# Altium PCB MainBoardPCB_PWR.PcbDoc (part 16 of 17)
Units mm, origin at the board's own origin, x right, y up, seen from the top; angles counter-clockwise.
Board outline 333.63 x 349.38 mm, 16 copper layers (L1, L2 (GND), L3 (Sign), L4 (GND), L5 (Sign), L6 (PWR/GND), L7(PWR/GND), L8 (PWR/GND), L9 (PWR/GND), L10 (PWR/GND), L11 (PWR/GND), L12 (Sign), L13 (GND), L14 (Sign), L15 (GND), L16), stack 2.503 mm thick; 2187 components, 1615 nets, 7987 pads, 1695 vias.
Unrouted connection lines stored in the file: 4757.
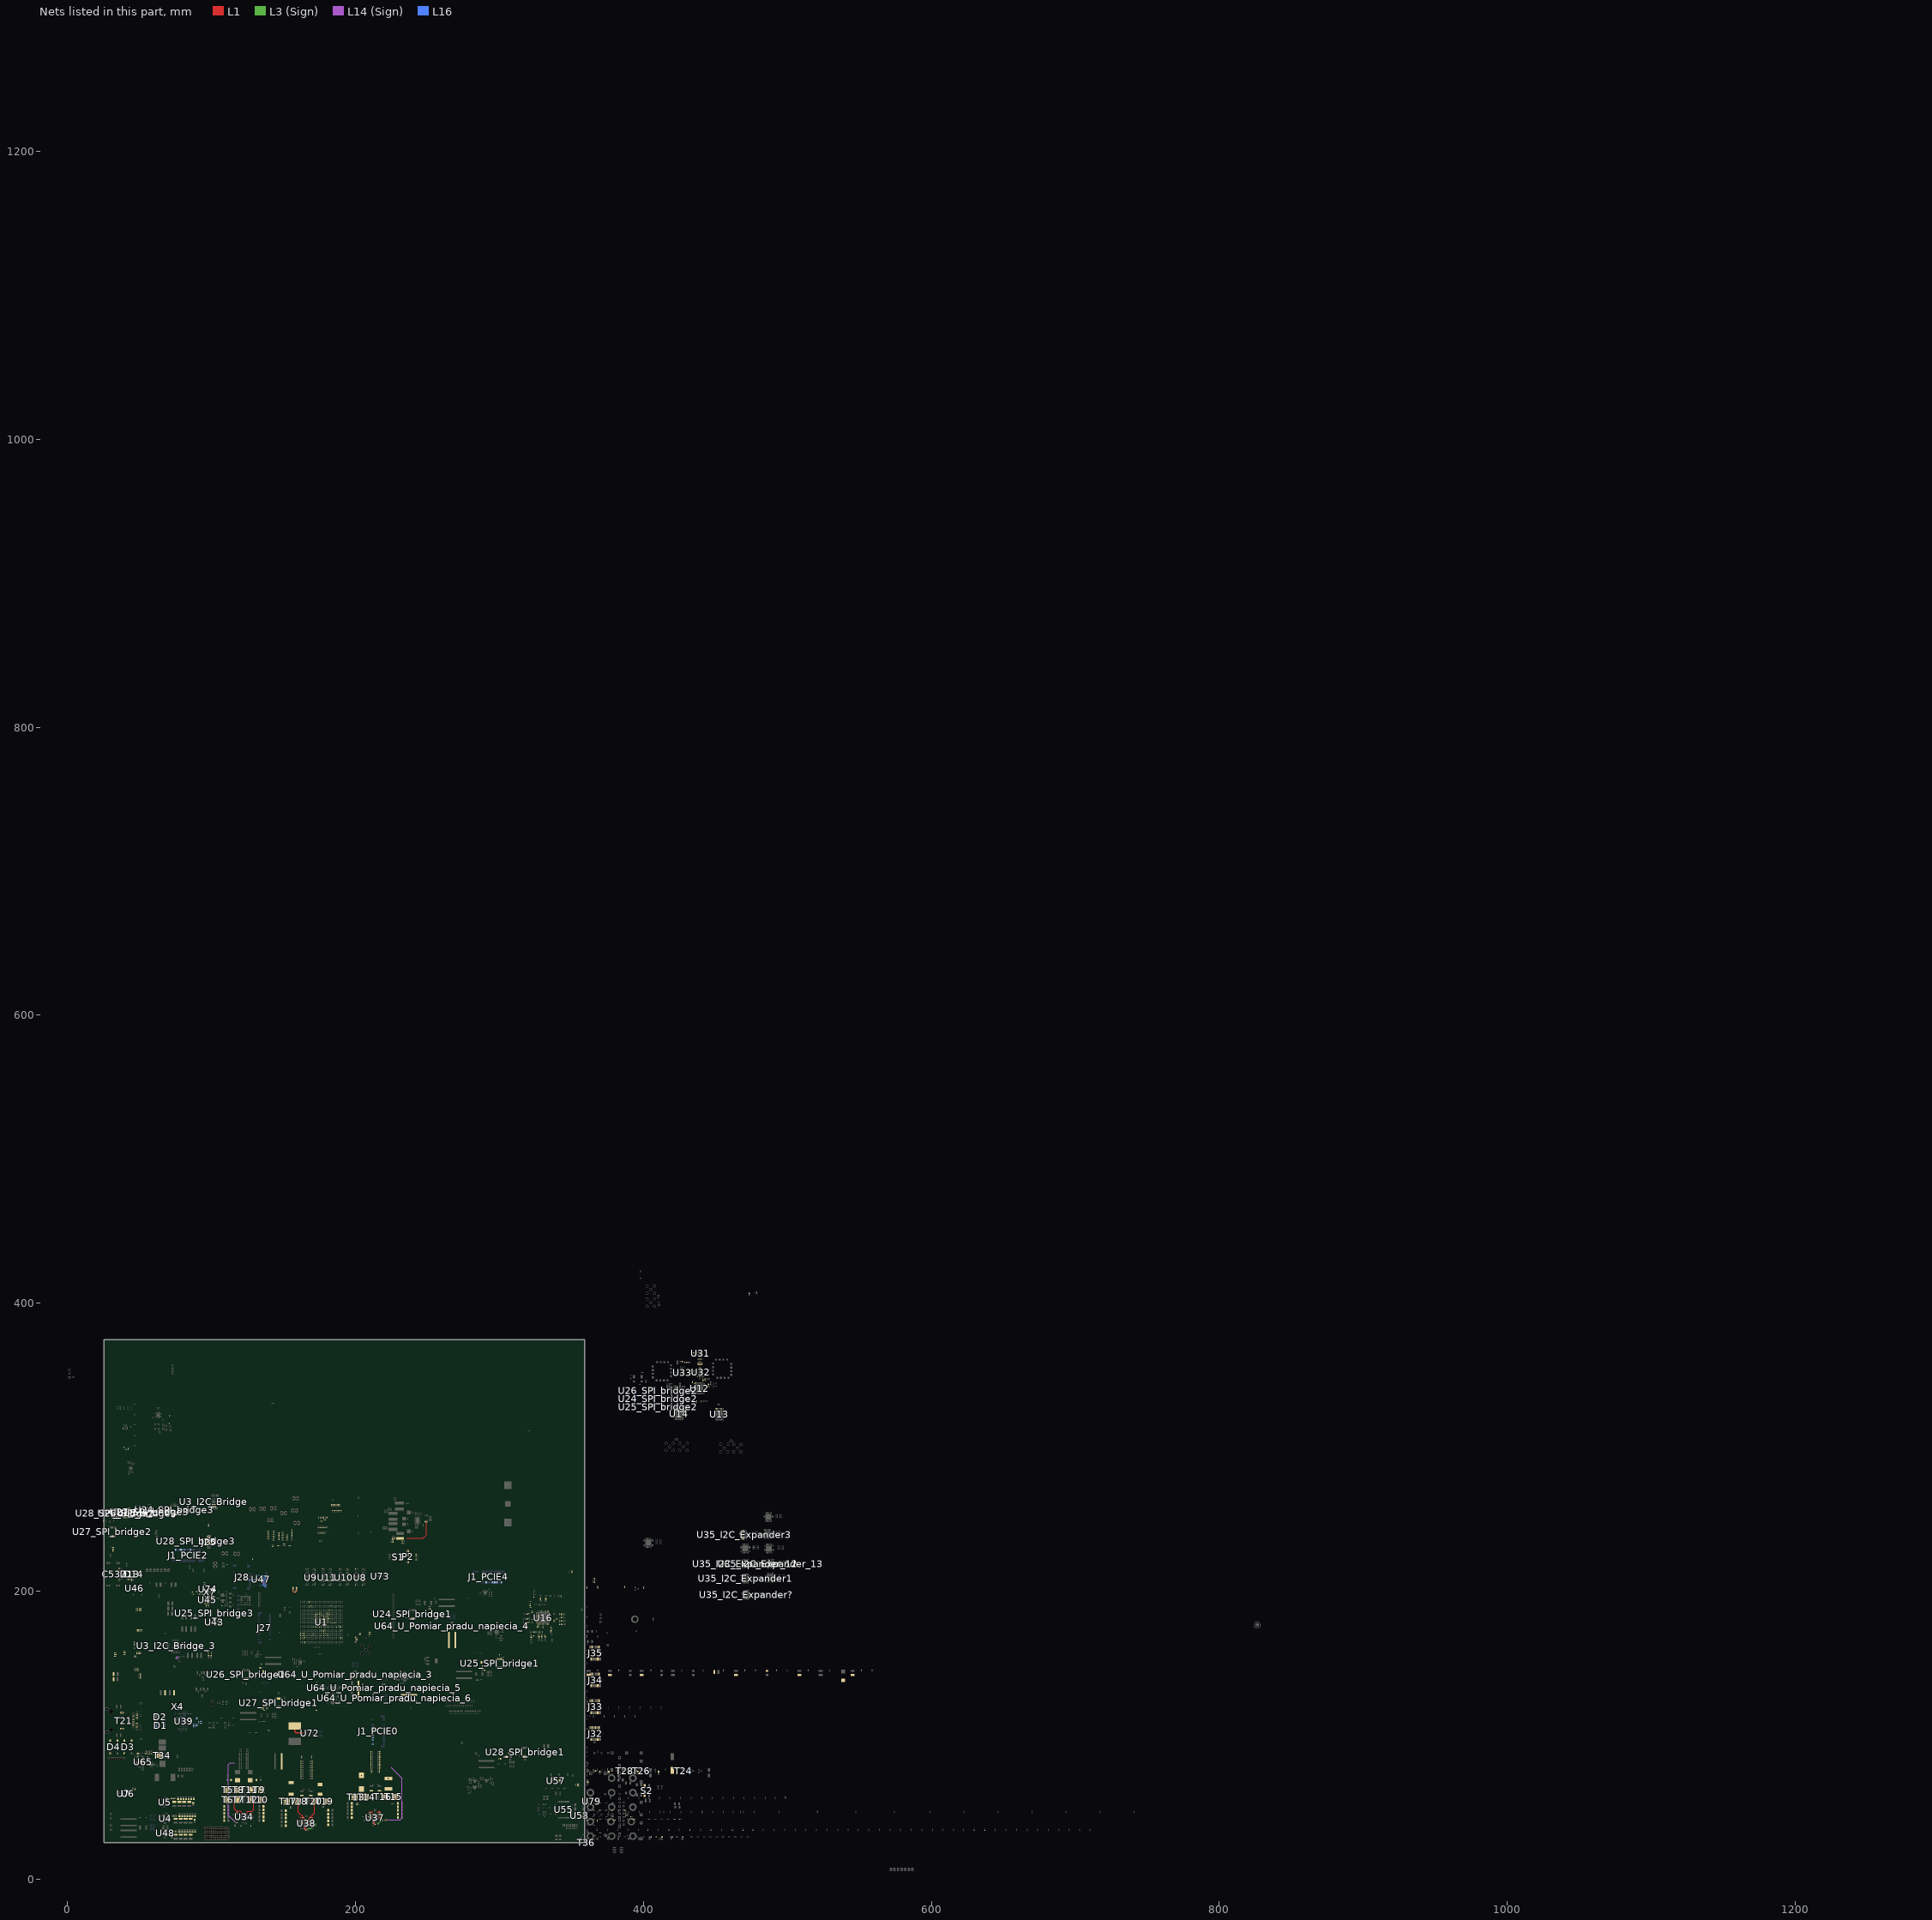
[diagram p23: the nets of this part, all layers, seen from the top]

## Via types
v1: diameter 0.5, hole 0.2, L1 to L16, 786 vias
v2: diameter 0.5/0.35/0.35/0.35/0.35/0.35/0.35/0.35/0.35/0.35/0.35/0.35/0.35/0.35/0.35/0.5 (per signal layer), hole 0.15, L1 to L16, tented both sides, 164 vias
v3: diameter 2.54, hole 1.02, L1 to L16, 152 vias
v4: diameter 0.5/0.35/0.35/0.35/0.35/0.35/0.35/0.35/0.35/0.35/0.35/0.35/0.35/0.35/0.35/0.5 (per signal layer), hole 0.2, L1 to L16, tented both sides, 100 vias
v5: diameter 0.45, hole 0.15, L1 to L16, 79 vias
v6: diameter 0.35/0/0.35 (per signal layer), hole 0.127, L1 to L3 (Sign), tented both sides, 78 vias
v7: diameter 0.45/0.45/0.45/0.45/0.45/0.45/0.45/0.45/0.45/0.45/0.45/0.45/0.45/0.45/0.45/0.45 (per signal layer), hole 0.15, L1 to L16, 65 vias
v8: diameter 0.4, hole 0.15, L1 to L16, 61 vias
v9: diameter 0.2, hole 0.1, L1 to L16, 35 vias
v10: diameter 0.5, hole 0.2, L1 to L16, tented both sides, 32 vias
v11: diameter 0.2/0/0.2 (per signal layer), hole 0.1, L1 to L3 (Sign), 28 vias
v12: diameter 0.4, hole 0.2, L1 to L16, 16 vias
v13: diameter 0.25, hole 0.2, L1 to L16, 16 vias
v14: diameter 0.3, hole 0.2, L1 to L16, 15 vias
v15: diameter 0.5/0.35/0.35/0.35/0.35/0.35/0.35/0.35/0.35/0.35/0.35/0.35/0.35/0.35/0.35/0.45 (per signal layer), hole 0.15, L1 to L16, tented both sides, 10 vias
v16: diameter 5, hole 3, L1 to L16, 9 vias
v17: diameter 0.2/0/0.2 (per signal layer), hole 0.1, L1 to L3 (Sign), tented both sides, 9 vias
v18: diameter 0.35/0/0.35 (per signal layer), hole 0.127, L1 to L3 (Sign), 7 vias
v19: diameter 0.35/0/0.35 (per signal layer), hole 0.127, L14 (Sign) to L16, tented both sides, 5 vias
v20: diameter 1.65, hole 1.65, L1 to L16, 4 vias
v21: diameter 1.15, hole 1.15, L1 to L16, 4 vias
v22: diameter 0.35, hole 0.127, L1 to L2 (GND), 2 vias
v23: diameter 0.4, hole 0.2, L1 to L16, tented both sides, 2 vias
v24: diameter 0.35, hole 0.127, L1 to L2 (GND), tented both sides, 2 vias
v25: diameter 0.508, hole 0.127, L1 to L2 (GND), 2 vias
v26: diameter 0.508, hole 0.127, L2 (GND) to L3 (Sign), 2 vias
v27: diameter 0.35, hole 0.127, L3 (Sign) to L6 (PWR/GND), tented both sides, 2 vias
v28: diameter 0.5, hole 0.2, L3 (Sign) to L6 (PWR/GND), tented both sides, 2 vias
v29: diameter 5.5, hole 3.5, L1 to L16, 1 vias
v30: diameter 0.45/0.45/0.45 (per signal layer), hole 0.15, L1 to L3 (Sign), 1 vias
v31: diameter 0.35/0.35/0.35 (per signal layer), hole 0.127, L1 to L3 (Sign), tented both sides, 1 vias
v32: diameter 0.45/0/0.45 (per signal layer), hole 0.15, L1 to L3 (Sign), tented both sides, 1 vias
v33: diameter 0.45/0/0.45 (per signal layer), hole 0.2, L14 (Sign) to L16, tented both sides, 1 vias
v34: diameter 0.35, hole 0.127, L2 (GND) to L3 (Sign), 1 vias

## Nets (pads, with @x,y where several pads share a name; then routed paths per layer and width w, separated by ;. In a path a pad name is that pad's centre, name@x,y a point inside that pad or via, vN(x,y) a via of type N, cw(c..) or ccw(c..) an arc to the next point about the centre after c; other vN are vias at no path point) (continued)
PWR_OUT_20V: C347.2 C348.2 C352.2 C353.2 C371.2 C372.2 C373.2 C374.2 C375.2 C376.2 C391.1 C392.2 C396.2 C397.1 C400.2 C401.2 C402.2 C403.2 C404.2 C405.2 C432.1 C433.2 C437.2 C438.1 C441.2 C442.2 C443.2 C444.2 C445.2 C446.2 C766.1 C767.1 C768.1 C769.1 C770.2 C771.2 C772.2 C773.2 C774.2 C775.2 C776.2 C777.2 C778.2 C779.2 C780.2 C781.2 R266.2 R268.1 R285.1 R303.1 R612.2 R614.2 R621.2 R622.2 R628.2 R686.2 T5.5 T5.6 T5.7 T5.8 T6.5 T6.6 T6.7 T6.8 T9.5 T9.6 T9.7 T9.8 T10.5 T10.6 T10.7 T10.8 T13.5 T13.6 T13.7 T13.8 T15.5 T15.6 T15.7 T15.8 T17.5 T17.6 T17.7 T17.8 T19.5 T19.6 T19.7 T19.8 U48.1 U48.8
  other v1: 95.25,27.75 96,27.75 96.75,27.75 97.5,27.75 98.25,27.75 99,27.75 99.75,27.75 100.5,27.75 101.25,27.75 102,27.75 102.75,27.75 103.5,27.75 104.25,27.75 105,27.75 105.75,27.75 106.5,27.75 107.25,27.75 108,27.75 108.75,27.75 109.5,27.75 110.25,27.75 111,27.75 95.625,28.5 96.375,28.5 97.125,28.5 97.875,28.5 98.625,28.5 99.375,28.5 100.125,28.5 100.875,28.5 101.625,28.5 102.375,28.5 103.125,28.5 103.875,28.5 104.625,28.5 105.375,28.5 106.125,28.5 106.875,28.5 107.625,28.5 108.375,28.5 109.125,28.5 109.875,28.5 110.625,28.5 111.375,28.5 112.125,28.5 95.25,29.25 96,29.25 96.75,29.25 97.5,29.25 98.25,29.25 99,29.25 99.75,29.25 100.5,29.25 101.25,29.25 102,29.25 102.75,29.25 103.5,29.25 104.25,29.25 105,29.25 105.75,29.25 106.5,29.25 107.25,29.25 108,29.25 108.75,29.25 109.5,29.25 110.25,29.25 111,29.25 111.75,29.25 95.625,30 96.375,30 97.125,30 97.875,30 98.625,30 99.375,30 100.125,30 100.875,30 101.625,30 102.375,30 103.125,30 103.875,30 104.625,30 105.375,30 106.125,30 106.875,30 107.625,30 108.375,30 109.125,30 109.875,30 110.625,30 111.375,30 112.125,30 95.25,30.75 96,30.75 96.75,30.75 97.5,30.75 98.25,30.75 99,30.75 99.75,30.75 100.5,30.75 101.25,30.75 102,30.75 102.75,30.75 103.5,30.75 104.25,30.75 105,30.75 105.75,30.75 106.5,30.75 107.25,30.75 108,30.75 108.75,30.75 109.5,30.75 110.25,30.75 111,30.75 111.75,30.75 95.625,31.5 96.375,31.5 97.125,31.5 97.875,31.5 98.625,31.5 99.375,31.5 100.125,31.5 100.875,31.5 101.625,31.5 102.375,31.5 103.125,31.5 103.875,31.5 104.625,31.5 105.375,31.5 106.125,31.5 106.875,31.5 107.625,31.5 108.375,31.5 109.125,31.5 109.875,31.5 110.625,31.5 111.375,31.5 112.125,31.5 95.25,32.25 96,32.25 96.75,32.25 97.5,32.25 98.25,32.25 99,32.25 99.75,32.25 100.5,32.25 101.25,32.25 102,32.25 102.75,32.25 103.5,32.25 104.25,32.25 105,32.25 105.75,32.25 106.5,32.25 107.25,32.25 108,32.25 108.75,32.25 109.5,32.25 110.25,32.25 111,32.25 111.75,32.25 95.625,33 96.375,33 97.125,33 97.875,33 98.625,33 99.375,33 100.125,33 100.875,33 101.625,33 102.375,33 103.125,33 103.875,33 104.625,33 105.375,33 106.125,33 106.875,33 107.625,33 108.375,33 109.125,33 109.875,33 110.625,33 111.375,33 112.125,33 95.25,33.75 96,33.75 96.75,33.75 97.5,33.75 98.25,33.75 99,33.75 99.75,33.75 100.5,33.75 101.25,33.75 102,33.75 102.75,33.75 103.5,33.75 104.25,33.75 105,33.75 105.75,33.75 106.5,33.75 107.25,33.75 108,33.75 108.75,33.75 109.5,33.75 110.25,33.75 111,33.75 111.75,33.75 95.625,34.5 96.375,34.5 97.125,34.5 97.875,34.5 98.625,34.5 99.375,34.5 100.125,34.5 100.875,34.5 101.625,34.5 102.375,34.5 103.125,34.5 103.875,34.5 104.625,34.5 105.375,34.5 106.125,34.5 106.875,34.5 107.625,34.5 108.375,34.5 109.125,34.5 109.875,34.5 110.625,34.5 111.375,34.5 112.125,34.5 95.25,35.25 96,35.25 96.75,35.25 97.5,35.25 98.25,35.25 99,35.25 99.75,35.25 100.5,35.25 101.25,35.25 102,35.25 102.75,35.25 103.5,35.25 104.25,35.25 105,35.25 105.75,35.25 106.5,35.25 107.25,35.25 108,35.25 108.75,35.25 109.5,35.25 110.25,35.25 111,35.25 111.75,35.25 95.625,36 96.375,36 97.125,36 97.875,36 98.625,36 99.375,36 100.125,36 100.875,36 101.625,36 102.375,36 103.125,36 103.875,36 104.625,36 105.375,36 106.125,36 106.875,36 107.625,36 108.375,36 109.125,36 109.875,36 110.625,36 111.375,36
  other v12: 67.617,31.412 68.417,31.412
PWR_Switch1_En: U6.A2 U35_I2C_Expander1.3
PWR_Switch1_Flag: U35_I2C_Expander1.2
PWR_Switch2_En: U7.A2 U35_I2C_Expander1.22
PWR_Switch2_Flag: U35_I2C_Expander1.18
PWR_SwitchR1_Flag: R29.1 U6.A3
PWR_SwitchR2_Flag: R30.1 U7.A3
RAM_DDR4_VTT: C722.2 C723.2 R31.2 R32.2 R33.2 R34.2 R35.2 R36.2 R37.2 R38.2 R39.2 R40.2 R41.2 R42.2 R43.2 R44.2 R45.2 R46.2 R47.2 R48.2 R49.2 R50.2 R51.2 R53.2 R55.2 R57.2 R59.2 R689.1 U73.8
RAM_Vcc1V2: C36.2 C220.1 C222.1 C223.2 C224.2 C225.2 C226.2 C227.2 C228.2 C229.2 C230.2 C231.2 C232.2 C233.2 C234.2 C235.2 C236.2 C237.2 C238.2 C239.2 C240.2 C241.2 C242.2 C244.1 C246.1 C247.2 C248.2 C249.2 C250.2 C251.2 C252.2 C253.2 C254.2 C255.2 C256.2 C257.2 C258.2 C259.2 C260.2 C261.2 C262.2 C263.2 C264.2 C265.2 C266.2 C741.2 C760.1 C761.2 R58.2 R165.2 R166.2 R169.2 R171.2 R297.2 R448_U_Pomiar_pradu_napiecia_4.2 R695.1 U1.A6 U1.B8 U1.C6 U1.D8 U1.E6 U1.G6 U1.J6 U1.L6 U1.M25 U1.N6 U1.R6 U1.T18 U1.T20 U1.T21 U1.U6 U8.A1 U8.A6 U8.B3 U8.B6 U8.C1 U8.D1 U8.D6 U8.F2 U8.F5 U8.G1 U8.G4 U8.G6 U8.J1 U8.J2 U8.J5 U8.J6 U8.L1 U8.L6 U8.R1 U8.T6 U9.A1 U9.A6 U9.B3 U9.B6 U9.C1 U9.D1 U9.D6 U9.F2 U9.F5 U9.G1 U9.G4 U9.G6 U9.J1 U9.J2 U9.J5 U9.J6 U9.L1 U9.L6 U9.R1 U9.T6 U10.A1 U10.A6 U10.B3 U10.B6 U10.C1 U10.D1 U10.D6 U10.F2 U10.F5 U10.G1 U10.G4 U10.G6 U10.J1 U10.J2 U10.J5 U10.J6 U10.L1 U10.L6 U10.R1 U10.T6 U11.A1 U11.A6 U11.B3 U11.B6 U11.C1 U11.D1 U11.D6 U11.F2 U11.F5 U11.G1 U11.G4 U11.G6 U11.J1 U11.J2 U11.J5 U11.J6 U11.L1 U11.L6 U11.R1 U11.T6 U64_U_Pomiar_pradu_napiecia_4.8 U64_U_Pomiar_pradu_napiecia_4.9 | length 50.7
  L1 w0.254: R297.2@221.201,41.215 222.24,41.215 v9(222.26,41.234)
  L14 (Sign) w0.254: v9(222.26,41.234) 231.218,41.234 232.456,42.473 232.456,69.878 v9@224.342,77.993
  L16 w0.254: v9@224.342,77.993 v9(224.342,77.996)
RAM_VrefA: C221.1 R166.1 R168.1 U8.M1
RAM_VrefB: C243.1 R169.1 R170.1 U10.M1
RAM_VrefC: C219.1 R165.1 R167.1 U9.M1
RAM_VrefD: C245.1 R171.1 R172.1 U11.M1
RefClk_Si53323_N: R253.1 R255.2 U31.7
RefClk_Si53323_P: C341.2 R252.1 R254.2 U31.6
RESET_N: R712.1 R713.2 U39.43
RESETB: U45.27 U74.4
RST_brigde: R757.1 U3_I2C_Bridge_3.24 U35_I2C_Expander?.28
SD_Card_CLK: J28.5 U47.C5 | length 6.8
  L16 w0.098: J28.5@126.749,207.781 129.739,207.781 130.112,208.153 U47.C5@133.439,208.153
SD_Card_en: R382.1 U47.C2
SetClk_Si53323_2: T36.1 U1.K12
SFP0_ABS: J32.6 R65.1
SFP0_LOS: J32.8 R66.1 U35_I2C_Expander3.28
SFP0_RS0: J32.7 R72.1 R74.2
SFP0_RS1: J32.9 R71.1 R73.2
SFP0_Rx_N: J32.19 U1.D5
SFP0_Rx_P: J32.18 U1.D6
SFP0_Tx_N: J32.12 U1.D1
SFP0_Tx_P: J32.13 U1.D2
SFP0_TxDis: J32.3 R68.1 U35_I2C_Expander3.27
SFP0_TxF: J32.2 R67.1 U35_I2C_Expander3.26
SFP0_VccR: C37.2 C38.1 J32.15 L1.2
SFP0_VccT: C39.2 C40.1 J32.16 L2.2
SFP1_ABS: J33.6 R135.1
SFP1_GND: R143.1 R144.1
SFP1_LOS: J33.8 R136.1 U35_I2C_Expander3.4
SFP1_RS0: J33.7 R142.1 R144.2
SFP1_RS1: J33.9 R141.1 R143.2
SFP1_Rx_N: J33.19 U1.C7 | length 2.1
  L14 (Sign) w0.072: 75.168,153.381 ccw(c75.168,156.118) 77.104,154.183
SFP1_Rx_P: J33.18 U1.C8 | length 2
  L14 (Sign) w0.072: 75.167,153.581 ccw(c75.167,156.121) 76.963,154.325
SFP1_Tx_N: J33.12 U1.C3
SFP1_Tx_P: J33.13 U1.C4
SFP1_TxDis: J33.3 R138.1 U35_I2C_Expander3.1
SFP1_TxF: J33.2 R137.1 U35_I2C_Expander3.24
SFP2_ABS: J34.6 R145.1
SFP2_GND: R153.1 R154.1
SFP2_LOS: J34.8 R146.1 U35_I2C_Expander3.3
SFP2_RS0: J34.7 R152.1 R154.2
SFP2_RS1: J34.9 R151.1 R153.2
SFP2_Rx_N: J34.19 U1.B5
SFP2_Rx_P: J34.18 U1.B6
SFP2_Tx_N: J34.12 U1.B1
SFP2_Tx_P: J34.13 U1.B2
SFP2_TxDis: J34.3 R148.1 U35_I2C_Expander3.17
SFP2_TxF: J34.2 R147.1 U35_I2C_Expander3.19
SFP3_ABS: J35.6 R155.1
SFP3_GND: R163.1 R164.1
SFP3_LOS: J35.8 R156.1 U35_I2C_Expander3.21
SFP3_RS0: J35.7 R162.1 R164.2
SFP3_RS1: J35.9 R161.1 R163.2
SFP3_Rx_N: J35.19 U1.A7
SFP3_Rx_P: J35.18 U1.A8
SFP3_Tx_N: J35.12 U1.A3
SFP3_Tx_P: J35.13 U1.A4
SFP3_TxDis: J35.3 R158.1 U35_I2C_Expander3.18
SFP3_TxF: J35.2 R157.1 U35_I2C_Expander3.2
SFP_IO_nReset: R756.1 U35_I2C_Expander3.14 U35_I2C_Expander?.1
SGMI_C_Rx_N: C484.1 U1.G26
SGMI_C_Rx_P: C483.1 U1.G25
SGMI_C_Tx_N: C482.1 U1.G30
SGMI_C_Tx_P: C479.1 U1.G29
SGMI_CLK_Out_N: R320.1 R321.1 R326.2 U39.34
SGMI_CLK_Out_P: R319.1 R321.2 R325.2 U39.33
SGMI_Rx_N: C484.2 U39.28
SGMI_Rx_P: C483.2 U39.27
SGMI_Tx_N: C482.2 R323.1 R328.2 U39.36
SGMI_Tx_P: C479.2 R322.1 R327.2 U39.35
Si53323_1_Q1_N: C330.1 R249.1 U31.9
Si53323_1_Q1_P: C325.1 R246.2 U31.10
Si53323_1_Q2_LVDS_N: C725.2 R386.2 R387.2 U1.AK4
Si53323_1_Q2_LVDS_P: C724.2 U1.AJ4
Si53323_1_Q2_N: R301.1 R385.2 U31.12
Si53323_1_Q2_P: R291.1 R384.2 U31.11
Si53323_2_CLK1_N: C330.2 R245.2 R248.2 R251.2 U32.4
Si53323_2_CLK1_P: C325.2 R245.1 R247.2 R250.2 U32.3
Si53323_2_Q1_N: C54.2 R537.2 U32.10
Si53323_2_Q1_P: C53.2 R536.1 U32.9
Si53323_2_Q2_LVDS_N: C727.2 R486.2 R487.2
Si53323_2_Q2_LVDS_P: C726.2
Si53323_2_Q2_N: R483.1 R485.2 U32.12
Si53323_2_Q2_P: R482.1 R484.2 U32.11
SMCLK_PCIE0: J1_PCIE0.26 R559_I2C_Bridge.1 U3_I2C_Bridge.2
SMCLK_PCIE1: R227_I2C_Bridge.1 U3_I2C_Bridge.4
SMCLK_PCIE2: J1_PCIE2.26 R225_I2C_Bridge.1 U3_I2C_Bridge.6
SMCLK_PCIE3: R223_I2C_Bridge.1 U3_I2C_Bridge.8
SMCLK_PCIE4: J1_PCIE4.26 R9_I2C_Bridge.1 U3_I2C_Bridge.11
SMDAT_PCIE0: J1_PCIE0.28 R560_I2C_Bridge.1 U3_I2C_Bridge.1
SMDAT_PCIE1: R558_I2C_Bridge.1 U3_I2C_Bridge.3
SMDAT_PCIE2: J1_PCIE2.28 R226_I2C_Bridge.1 U3_I2C_Bridge.5
SMDAT_PCIE3: R224_I2C_Bridge.1 U3_I2C_Bridge.7
SMDAT_PCIE4: J1_PCIE4.28 R10_I2C_Bridge.1 U3_I2C_Bridge.10
SPI1_CLK: J25.1 R132.2 R803.1 U15.14 U24_SPI_bridge2.3 U24_SPI_bridge3.3 U25_SPI_bridge2.3 U25_SPI_bridge3.3 U26_SPI_bridge2.3 U26_SPI_bridge3.3 U27_SPI_bridge2.3 U27_SPI_bridge3.3 U28_SPI_bridge2.3 U28_SPI_bridge2.14 U28_SPI_bridge3.3
SPI1_CLK: 
SPI1_CS: J25.4 R123.1 R124.1 R806.1 U15.11 U24_SPI_bridge2.6 U24_SPI_bridge3.6 U25_SPI_bridge2.6 U25_SPI_bridge3.6 U26_SPI_bridge2.6 U26_SPI_bridge3.6 U27_SPI_bridge2.6 U27_SPI_bridge3.6 U28_SPI_bridge2.6 U28_SPI_bridge3.6
SPI1_MISO: J25.3 R807.1 U15.13 U24_SPI_bridge2.4 U24_SPI_bridge3.4 U25_SPI_bridge2.4 U25_SPI_bridge3.4 U26_SPI_bridge2.4 U26_SPI_bridge3.4 U27_SPI_bridge2.4 U27_SPI_bridge3.4 U28_SPI_bridge2.4 U28_SPI_bridge3.4
SPI1_MISO: U12.51 U26_SPI_bridge2.13
SPI1_MOSI: U35_I2C_Expander_13.19
SPI1_MOSI: J25.2 R808.1 U12.52 U15.12 U24_SPI_bridge2.5 U24_SPI_bridge3.5 U25_SPI_bridge2.5 U25_SPI_bridge3.5 U26_SPI_bridge2.5 U26_SPI_bridge2.12 U26_SPI_bridge3.5 U27_SPI_bridge2.5 U27_SPI_bridge3.5 U28_SPI_bridge2.5 U28_SPI_bridge3.5
SPI2_CLK: U13.50 U25_SPI_bridge2.14
SPI2_MISO: U13.51 U25_SPI_bridge2.13
SPI2_MOSI: U13.52 U25_SPI_bridge2.12
SPI3_CLK: U14.50 U24_SPI_bridge2.14
SPI3_MISO: U14.51 U24_SPI_bridge2.13
SPI3_MOSI: U14.52 U24_SPI_bridge2.12
SPI_05028_CS: U35_I2C_Expander_13.24
SPI_05028_CS: R125.2 R127.1 R139.2 R240_SPI_bridge2.1 U16.24 U28_SPI_bridge2.11
SPI_05028_MISO: R1.1 R2.2 R133.1 U16.60
SPI_6952_1_CS: U35_I2C_Expander_13.4
SPI_6952_1_CS: R236_SPI_bridge2.1 U12.1 U26_SPI_bridge2.11
SPI_6952_2_CS: R233_SPI_bridge2.1 U13.1 U25_SPI_bridge2.11
SPI_6952_3_CS: R231_SPI_bridge2.1 U14.1 U24_SPI_bridge2.11
SPI_CLK_PCIE0: J1_PCIE0.22 U24_SPI_bridge1.14
SPI_CLK_PCIE1: U25_SPI_bridge1.14
SPI_CLK_PCIE2: J1_PCIE2.22 U26_SPI_bridge1.14
SPI_CLK_PCIE3: U27_SPI_bridge1.14
SPI_CLK_PCIE4: J1_PCIE4.22 U28_SPI_bridge1.14
SPI_CNV: U35_I2C_Expander_13.28
SPI_DAC_CS: R236_SPI_bridge3.1 U26_SPI_bridge3.11 U30.14
SPI_DAC_CS: U35_I2C_Expander_13.1
SPI_FPGA_CLK: U1.AB15 U15.3
SPI_FPGA_CS: R365.2 U1.AG13 U15.6
SPI_FPGA_MISO: U1.AD15 U15.4
SPI_FPGA_MOSI: U1.AE15 U15.5
SPI_FPGA_nOE: U15.9
SPI_MISO_PCIE0: J1_PCIE0.18 U24_SPI_bridge1.13
SPI_MISO_PCIE1: U25_SPI_bridge1.13
SPI_MISO_PCIE2: J1_PCIE2.18 U26_SPI_bridge1.13
SPI_MISO_PCIE3: U27_SPI_bridge1.13
SPI_MISO_PCIE4: J1_PCIE4.18 U28_SPI_bridge1.13
SPI_MOSI_PCIE0: J1_PCIE0.20 U24_SPI_bridge1.12
SPI_MOSI_PCIE1: U25_SPI_bridge1.12
SPI_MOSI_PCIE2: J1_PCIE2.20 U26_SPI_bridge1.12
SPI_MOSI_PCIE3: U27_SPI_bridge1.12
SPI_MOSI_PCIE4: J1_PCIE4.20 U28_SPI_bridge1.12
SPI_nCS_1_PCIE0: J1_PCIE0.16 R231_SPI_bridge1.1 U24_SPI_bridge1.11
SPI_nCS_1_PCIE1: R233_SPI_bridge1.1 U25_SPI_bridge1.11
SPI_nCS_1_PCIE2: J1_PCIE2.16 R236_SPI_bridge1.1 U26_SPI_bridge1.11
SPI_nCS_1_PCIE3: R238_SPI_bridge1.1 U27_SPI_bridge1.11
SPI_nCS_1_PCIE4: J1_PCIE4.16 R240_SPI_bridge1.1 U28_SPI_bridge1.11
SPI_nCS_2_PCIE0: J1_PCIE0.14
SPI_nCS_2_PCIE1: 
SPI_nCS_2_PCIE2: J1_PCIE2.14
SPI_nCS_2_PCIE3: 
SPI_nCS_2_PCIE4: J1_PCIE4.14
SPI_PCIE_SWITCH: U35_I2C_Expander_12.1
SPI_RESET: U35_I2C_Expander_13.25
SS1_1: C639.2 U37.28 | length 1.7
  L1 w0.254: C639.2@209.831,42.359 209.836,42.359 210.28,42.803 210.566,42.803 210.623,42.859 U37.28@211.295,42.859
SS1_2: C647.2 U38.28 | length 1.6
  L1 w0.254: C647.2@162.233,39.015 U38.28@163.783,39.015
SS2_1: C640.2 U37.13 | length 1.6
  L1 w0.254: U37.13@215.795,42.859 216.212,42.859 216.712,42.359 C640.2@217.165,42.359
SS2_2: C648.2 U38.13 | length 1.5
  L1 w0.254: U38.13@168.283,39.015 168.896,39.015 169.108,38.803 C648.2@169.734,38.803
SUSCLK: J27.60
SW1: C346.2 L9.1 R610.2 R613.2 T5.1 T5.2 T5.3 T6.1 T6.2 T6.3 T7.5 T7.6 T7.7 T7.8 T8.5 T8.6 T8.7 T8.8 U34.24 | length 13.3
  L1 w0.254: T7.8@115.802,53.156 115.802,48.85 117.646,47.007 ; R610.2@117.646,45.463 C346.2@117.646,46.421 117.646,47.007 ; U34.24@120.977,45.406 120.977,46.41 120.066,47.321 117.96,47.321 117.646,47.007
SW1_1: C390.2 L11.1 R288.2 R619.2 T13.1 T13.2 T13.3 T14.5 T14.6 T14.7 T14.8 U37.24 | length 5.1
  L1 w0.254: R619.2@209.916,45.309 C390.2@209.916,46.316 209.921,46.316 210.064,46.459 210.064,46.691 210.259,46.886 211.495,46.886 211.795,46.586 U37.24@211.795,44.86
SW1_2: C431.2 L19.1 R306.2 R625.1 T17.1 T17.2 T17.3 T18.5 T18.6 T18.7 T18.8 U38.24 | length 17.3
  L1 w0.254: T18.8@160.326,53.955 160.327,46.511 163.383,43.454 C431.2@163.383,42.843 ; R625.1@161.618,42.063 161.618,42.439 162.023,42.843 C431.2@163.383,42.843 ; U38.24@164.283,41.015 164.283,42.671 164.135,42.82 163.406,42.82 C431.2@163.383,42.843
SW2: C350.2 L10.1 R611.2 R616.2 T9.1 T9.2 T9.3 T10.1 T10.2 T10.3 T11.5 T11.6 T11.7 T11.8 T12.5 T12.6 T12.7 T12.8 U34.17 | length 13.1
  L1 w0.254: U34.17@124.477,45.406 124.477,46.169 125.246,46.938 127.646,46.938 127.794,46.789 ; R611.2@127.969,45.198 127.969,45.986 127.799,46.156 C350.2@127.794,46.156 127.794,46.789 ; T12.5@129.177,53.156 129.177,48.172 127.794,46.789
SW2_1: C394.2 L12.1 R298.2 R620.2 T15.1 T15.2 T15.3 T16.5 T16.6 T16.7 T16.8 U37.17 | length 5
  L1 w0.254: U37.17@215.295,44.86 215.295,46.212 216.119,47.036 216.706,47.036 216.978,46.764 216.978,46.382 C394.2@217.045,46.316 217.05,46.311 217.05,45.314 R620.2@217.055,45.309
SW2_2: C435.2 L20.1 R302.1 R316.2 T19.1 T19.2 T19.3 T20.5 T20.6 T20.7 T20.8 U38.17 | length 17.8
  L1 w0.254: U38.17@167.783,41.015 167.783,42.456 168.186,42.858 C435.2@168.633,42.858 ; R302.1@170.334,41.515 170.334,42.698 170.174,42.858 C435.2@168.633,42.858 ; T20.8@171.578,54.055 171.578,45.807 168.633,42.863 C435.2@168.633,42.858
SYNC_PCIE0_N: J1_PCIE0.46 U1.AJ12
SYNC_PCIE0_P: J1_PCIE0.44 U1.AH12
SYNC_PCIE1_N: U1.AF11
SYNC_PCIE1_P: U1.AF12
SYNC_PCIE2_N: J1_PCIE2.46 U1.AH11
SYNC_PCIE2_P: J1_PCIE2.44 U1.AG11
SYNC_PCIE3_N: U1.AK11
SYNC_PCIE3_P: U1.AJ11
SYNC_PCIE4_N: J1_PCIE4.46 U1.AK10
SYNC_PCIE4_P: J1_PCIE4.44 U1.AJ10
TD_A_N: D1.2 D1.7 T21.10 U39.2
TD_A_P: D1.1 D1.8 T21.11 U39.1
TD_B_N: D1.4 D1.5 T21.5 U39.5
TD_B_P: D1.3 D1.6 T21.4 U39.4
TD_C_N: D2.2 D2.7 T21.2 U39.8
TD_C_P: D2.1 D2.8 T21.3 U39.7
TD_D_N: D2.4 D2.5 T21.9 U39.11
TD_D_P: D2.3 D2.6 T21.8 U39.10
TRK1_1: U37.32
TRK1_2: U38.32
TRK2_1: U37.9
TRK2_2: U38.9
TTC_0: R810.1
TTC_3: R804.1
uart0_RxD: R779.1 U57.13
uart0_TxD: R778.1 U57.14
uart1_RxD: U1.AH13 U79.14
uart1_TxD: U1.AK13 U79.13
US+_DxN: R279.1 R286.1 U1.V15
US+_DxP: R282.1 R283.1 U1.V14
US+_GND_PS_ADC: C627.1 C628.1 FB39.2 U1.W21
US+_GNDADC: C629.1 C630.1 FB41.2 U1.R14 U1.U14 U1.U15
US+_MGTRref: R173.1 U1.K7
US+_MGTRref_K8: R695.2 U1.K8
US+_POR_OVE: R693.1 U1.Y6
US+_Pudc_B: R694.2 R696.1 U1.W7
US+_Vcc_PS_ADC: C627.2 C628.2 FB38.2 U1.W22
US+_Vcc_PS_Batt: B1.1 C747.1 C748.2 R276.1 U1.U20
US+_Vcc_PS_DDR_504: C616.2 C617.2 C618.2 C619.2 C620.2 C621.2 C622.2 C753.1 C754.2 C755.2 L18.2 R220.2 U1.AA24 U1.AB27 U1.AC25 U1.AD28 U1.AE26 U1.AG27 U1.AK26 | length 24.7
  L1 w0.254: 235.547,236.679 247.007,236.679 249.205,238.876 249.205,247.974 R220.2@249.13,248.049 248.58,248.049 248.33,248.298 C616.2@248.32,248.298
US+_Vcc_PS_DDR_PLL: C631.2 C632.2 FB42.2 U1.U18 U1.U19
US+_Vcc_PS_IntFp: C738.1 C739.1 C740.2 C744.2 C745.2 C751.1 C752.2 C762.1 C763.2 R271.2 R617.2 U1.AA18 U1.AA20 U1.AA21 U1.AA22 U1.L11 U1.L13 U1.L17 U1.M12 U1.M14 U1.M16 U1.M18 U1.N11 U1.N13 U1.N15 U1.N17 U1.P12 U1.P14 U1.P16 U1.R10 U1.R11 U1.R13 U1.R17 U1.T9 U1.T10 U1.T12 U1.T16 U1.U8 U1.U9 U1.U10 U1.U11 U1.U13 U1.U17 U1.V8 U1.V10 U1.V12 U1.V16 U1.V17 U1.V18 U1.V19 U1.W11 U1.W13 U1.W15 U1.W17 U1.W19 U1.W20 U1.Y12 U1.Y14 U1.Y16 U1.Y17 U1.Y18 U1.Y19 U1.Y20 U1.Y22 U72.8 U72.9 | length 57.3
  L1 w0.164: 161.617,101.632 161.712,101.728 163.858,101.728
  L1 w0.912: R617.2@157.952,106.38 157.952,102.49 158.81,101.632 161.617,101.632
  L14 (Sign) w0.254: 113.053,80.785 v9(115.802,80.785) ; 113.12,80.758 111.8,79.439 111.8,44.287 v1@116.988,39.099
  other v1: 116.921,39.126
US+_Vcc_PS_IntFpDDR: C764.1 C765.2
US+_VccADC: C629.2 C630.2 FB40.2 U1.R15
US+_VN: U1.T15
US+_VP: U1.T14
US_JTAG_CLK: U53.12
US_JTAG_TDI: U53.14
US_JTAG_TDO: U53.11
US_JTAG_TMS: U53.13
US_JTAG_Vcc: U53.15
US_PADI: C535.2 R374.1 U1.M21 X5.1 | length 3.5
  L1 w0.2: X5.1@156.644,202.242 X5.1@156.624,202.222 C535.2@156.624,200.432 156.624,199.714 156.999,199.339 R374.1@157.424,199.339
US_PADO: C536.2 R374.2 U1.N21 X5.2 | length 3.5
  L1 w0.2: R374.2@158.324,199.339 158.749,199.339 159.124,199.714 C536.2@159.124,200.432 X5.2@159.124,202.222
US_PS_DONE: R357.1 U1.N22 U43.6
US_PS_Err_Out: U1.R22 U43.3
US_PS_Err_Status: U1.R20 U43.4
US_PS_Init_B: R353.2 U1.N18 U43.5
US_PS_JTAG_TCK: R346.2 U1.L19
US_PS_JTAG_TDI: R347.2 U1.L20
US_PS_JTAG_TDO: U1.M20
US_PS_JTAG_TMS: R348.2 U1.L21
US_PS_Mode0: P2.4 R349.1 S1.1 U1.R18
US_PS_Mode2: P2.2 R351.1 S1.3 U1.P21
US_PS_Mode3: P2.1 R352.1 S1.4 U1.P22
US_PS_Prog_B: R356.2 R367.1 S2.1 S2.2 U1.M19
US_PS_Ref_Clk: R375.2 U1.P19
USB2_CLK: R362.2 U45.1
USB2_D0: R116.2 U45.3
USB2_D1: R117.2 U45.4
USB2_D2: R115.2 U45.5
USB2_D3: R119.2 U45.6
USB2_D4: R120.2 U45.7
USB2_D5: R121.2 U45.9
USB2_D6: R122.2 U45.10
USB2_D7: R802.1 U45.13
USB2_DIR: R800.1 U45.31
USB2_NXT: R801.1 U45.2
USB2_STP: R118.2 U45.29
USB_D_N: C537.2 D13.2 U45.19
USB_D_P: C537.3 D13.1 U45.18
USB_En_Vout: U45.17 U46.A2
USB_OSC_IN: C736.2 R491.1 U45.26 X7.1
USB_OSC_Out: C737.2 R491.2 U45.25 X7.3
USB_RS0: R376.1 U45.8
USB_RS1: R377.1 U45.11
USB_RS2: R378.1 U45.14
USB_RX_C_N: C537.5 C543.2 D14.1 D14.10
USB_RX_C_P: C537.6 C542.2 D14.2 D14.9
USB_RX_N: C543.1 U1.J26
USB_RX_P: C542.1 U1.J25
USB_TX_C_N: C537.8 C541.2 D14.4 D14.7
USB_TX_C_P: C537.9 C540.2 D14.5 D14.6
USB_TX_N: C541.1 U1.H28
USB_TX_P: C540.1 U1.H27
USB_Vbus: R490.1 U45.22
USB_Vdd33: C731.2 U45.20
USB_Vout: C538.2 C539.2 C734.2 FB26.1 R490.2 U46.C2 U46.D1 U46.D2 U46.E1 U46.E2 U46.F1 U46.F2
uSD_CLK: R96.2 R97.1 U47.C1 | length 2.8
  L16 w0.098: U47.C1@135.039,208.153 135.928,208.153 136.436,207.645 R96.2@137.599,207.645
uSD_CMD: R95.2 U47.D2 | length 5.4
  L14 (Sign) w0.098: v19(134.639,207.753) 135.579,207.753 136.516,206.816 v19(136.516,204.953)
  L16 w0.098: v19(136.516,204.953) 136.948,204.521 R95.2@137.599,204.521
uSD_D0: R87.2 U47.D1 | length 3.8
  L16 w0.098: U47.D1@135.039,207.753 135.336,207.753 136.231,206.858 136.231,206.326 136.995,205.562 R87.2@137.599,205.562
uSD_D1: R88.2 U47.E1 | length 5.5
  L16 w0.098: U47.E1@135.039,207.353 135.903,206.489 135.903,204.229 136.652,203.479 R88.2@137.599,203.479
uSD_D2: R89.2 U47.A1 | length 4.1
  L16 w0.098: U47.A1@135.039,208.953 135.039,210.223 135.585,210.769 R89.2@137.599,210.769
uSD_D3: R90.2 U47.B1 | length 2.6
  L16 w0.098: U47.B1@135.039,208.553 135.299,208.553 135.433,208.686 R90.2@137.599,208.686
uSD_D4: R91.2 U47.B2 | length 3.5
  L14 (Sign) w0.098: v19(134.639,208.553) 134.639,208.693 v19(135.611,209.664)
  L16 w0.098: v19(135.611,209.664) 135.679,209.664 135.742,209.728 R91.2@137.599,209.728
V_KEY: C609.2 R647.2 R648.1 R653.1 T24.1 T26.1 T28.1
V_PoE+: C595.2 C596.2 D3.1 D4.1 D27.1 R149.2 R324.2 T34.5 U65.18
  other v5: 65.48,85.852 63.03,85.889 39.675,86.991 58.578,87.219 29.683,87.244 54.875,87.307 56.704,87.317
  other v7: 29.25,83.25 30,83.25 30.75,83.25 31.5,83.25 32.25,83.25 33,83.25 33.75,83.25 34.5,83.25 35.25,83.25 36,83.25 36.75,83.25 37.5,83.25 38.25,83.25 39,83.25 28.875,84 29.625,84 30.375,84 31.125,84 31.875,84 32.625,84 33.375,84 34.125,84 34.875,84 35.625,84 36.375,84 37.125,84 37.875,84 38.625,84 39.375,84 50.25,87 51,87 51.75,87 52.5,87 53.25,87
VBB: C344.1 R257.1 U33.3 U33.4
VC1~: D3.4 T21.13
VC2~: D3.3 T21.14
VC3~: D4.4 T21.15
VC4~: D4.3 T21.16
Vcc_Aux_PCIE_PCIE0: C1_PCIE0.2 C2_PCIE0.2 C3_PCIE0.2 FB1_PCIE0.1 J1_PCIE0.2 J1_PCIE0.4
Vcc_Aux_PCIE_PCIE1: C1_PCIE1.2 C2_PCIE1.2 C3_PCIE1.2 FB1_PCIE1.1
Vcc_Aux_PCIE_PCIE2: C1_PCIE2.2 C2_PCIE2.2 C3_PCIE2.2 FB1_PCIE2.1 J1_PCIE2.2 J1_PCIE2.4
Vcc_Aux_PCIE_PCIE3: C1_PCIE3.2 C2_PCIE3.2 C3_PCIE3.2 FB1_PCIE3.1
Vcc_Aux_PCIE_PCIE4: C1_PCIE4.2 C2_PCIE4.2 C3_PCIE4.2 FB1_PCIE4.1 J1_PCIE4.2 J1_PCIE4.4
Vcc_CLK_Mux_Fine: C326.2 C327.2 C328.2 C329.2 FB23.2 R250.1 R251.1 R259.1 R260.1 R386.1 R486.1 R488.2 U31.5 U32.5
Vcc_SFP_0: R155.2 R156.2 R157.2 R158.2 R161.2 R162.2
VCCINT: C598.2 D26.2 R669.1 U65.4 U65.14 | length 3.4
  L1 w0.254: 47.095,80.629 47.099,80.633 48.073,80.633 R669.1@48.076,80.636 49.503,80.636 49.574,80.707 U65.4@50.492,80.707
VCCO_1: C398.2 R289.2 R293.1 R295.1 R296.1 U37.2 U37.4 | length 13.9
  L1 w0.254: U37.2@212.295,40.359 C398.2@212.295,39.006 212.864,39.006 213.268,39.41 ; U37.4@213.295,40.359 213.295,39.83 213.268,39.803 213.268,39.41 ; R293.1@214.795,38.066 R289.2@213.795,38.066 213.445,38.066 213.268,38.243 213.268,39.41 ; R296.1@218.005,43.359 v11(218.43,43.359)
  L3 (Sign) w0.254: v11(214.795,38.016) 215.366,38.016 218.522,41.172 218.522,43.267 v11(218.43,43.359)
VCCO_2: C439.2 R307.2 R310.1 R313.1 R314.1 U38.2 U38.4 | length 16.8
  L1 w0.254: U38.2@164.783,36.515 164.783,35.792 164.703,35.712 ; R307.2@165.454,34.152 165.208,34.152 165.021,34.339 165.021,34.6 164.833,34.787 164.563,34.787 C439.2@164.433,34.917 164.433,35.442 164.703,35.712 ; R307.2@165.608,34.087 R310.1@166.533,34.087 v11(166.533,34.037) ; U38.4@165.783,36.515 165.783,35.992 165.504,35.712 164.703,35.712 ; R314.1@170.674,39.685 v11(171.099,39.685)
  L3 (Sign) w0.254: v11(166.533,34.037) 167.533,35.037 168.936,35.037 170.864,36.965 172.502,36.965 172.502,38.282 v11(171.099,39.685)
VDD_APLL1: C88.1 C110.2 FB13.2 U16.49
VDD_APLL2: C89.1 C127.2 FB15.2 U16.37
VDD_CLK_MUX_DIV_3.3V: C336.2 C337.2 C338.2 C340.2 FB24.2 U33.1 U33.8 U33.9 U33.12
VDD_DIG: C93.1 C165.2 C590.2 FB21.2 FB37.1 R1.2 R125.1 R127.2 R128.2 R366.1 R544.2 U16.8
VDD_IN0: C63.1 C101.2 FB8.2 U16.3
VDD_IN1: C64.1 C105.2 FB10.2 U16.16
VDD_IN2: C67.1 C109.2 FB12.2 U16.9
VDD_IN3: C70.1 C126.2 FB14.2 U16.4
VDD_TCXO: C92.1 C148.2 FB19.2 U16.19
VDD_XO: C90.1 C144.2 FB17.2 U16.42
VDDO_0: C75.1 C143.2 FB16.2 U16.21
VDDO_1: C76.1 C147.2 FB18.2 U16.25
VDDO_6: C77.1 C164.2 FB20.2 U16.59
VDDO_7: C81.1 C180.2 FB22.2 U16.63
VDDO_23: C82.1 C102.2 FB9.2 U16.30
VDDO_45: C83.1 C106.2 FB11.2 U16.50
VLDO: C544.2 R383.2 U47.B4
Vout1_1: C406.2 C407.2 C408.2 C409.2 C410.2 C411.2 C412.2 C413.2 C414.2 C415.2 C416.2 C417.2 L11.2 R448_U_Pomiar_pradu_napiecia_3.1 U64_U_Pomiar_pradu_napiecia_3.10 | length 0
  L16 w0.254: 194.963,41.245 194.982,41.265
  other v5: 204.133,72.064
Vout1_2: C447.2 C448.2 C449.2 C450.2 C451.2 C452.2 C453.2 C454.2 C455.2 C456.2 C457.2 C458.2 L19.2 R448_U_Pomiar_pradu_napiecia_5.1 U64_U_Pomiar_pradu_napiecia_5.10
Vout2_1: C418.2 C419.2 C420.2 C421.2 C422.2 C423.2 C424.2 C425.2 C426.2 C427.2 C428.2 C429.2 L12.2 R448_U_Pomiar_pradu_napiecia_4.1 U64_U_Pomiar_pradu_napiecia_4.10
  other v5: 222.802,69.878
Vout2_2: C459.2 C460.2 C461.2 C462.2 C463.2 C464.2 C465.2 C466.2 C467.2 C468.2 C469.2 C470.2
Vout_1_Selector: C4.1 C5.1 C6.1 C7.1 C8.2 C9.2 C10.2 C11.2 C20.2 C21.2 C22.2 C23.2 C24.2 C25.2 C26.2 C27.2 R15.2 U4.7 U5.1 U5.8
  other v12: 67.41,42.35 67.229,53.095 68.029,53.095
Vout_2_Selector: C12.1 C13.1 C14.1 C15.1 C16.2 C17.2 C18.2 C19.2 C28.2 C29.2 C30.2 C31.2 C32.2 C33.2 C34.2 C35.2 R677.2 R678.2 U4.1 U4.8 U48.7
  other v12: 67.617,32.112 67.41,41.65 68.21,41.65
Vout_5V@10A_INA: L20.2 R448_U_Pomiar_pradu_napiecia_6.1 U64_U_Pomiar_pradu_napiecia_6.10 | length 0
  L16 w0.254: 185.2,48.06 185.204,48.06
VPHY_FTDI: C661.2 C662.2 FB44.2 U55.4
VPLL_FTDI: C659.2 C660.2 FB43.2 U55.9
VREF+_1: C61.2 C62.2 FB3.2 U12.44
VREF+_2: C73.2 C74.2 FB5.2 U13.44
VREF+_3: C57.2 C58.2 FB2.2 U14.44
VVCO+_1: C86.2 C87.2 FB6.2 U12.39
VVCO+_2: C97.2 C98.2 FB7.2 U13.39
VVCO+_3: C68.2 C69.2 FB4.2 U14.39
WR_LMK_CLK_HF1_N: U1.AK5 U16.26
WR_LMK_CLK_HF1_P: U1.AJ5 U16.27
WR_LMK_CLK_HF2_N: U1.AK2 U16.32
WR_LMK_CLK_HF2_P: U1.AK3 U16.31
WR_LMK_CLK_HF3_N: U16.33
WR_LMK_CLK_HF3_P: U16.34
WR_LMK_CLK_HF4_N: U16.52
WR_LMK_CLK_HF4_P: U16.51
WR_LMK_CLK_HF5_N: U16.53
WR_LMK_CLK_HF5_P: U16.54
WR_LMK_CLK_HF6_N: U16.58
WR_LMK_CLK_HF6_P: U16.57
WR_LMK_CLK_HF7_N: U16.61
WR_LMK_CLK_HF7_P: U16.62
WR_LMK_CLK_IN_N: C594.2 R311.1 U16.2
WR_LMK_CLK_IN_P: C593.2 R311.2 U16.1
WR_LMK_CLK_LF_N: U16.15 U16.23
WR_LMK_CLK_LF_P: U16.14 U16.22
WR_Source_CLK_N: C594.1 U13.6
WR_Source_CLK_P: C593.1 U13.7
X1: C481.2 R335.2 U39.14 X4.1
X2: C480.2 R335.1 U39.15 X4.3
XO_LMK05028_P: C589.2 U16.43
pads on no net: C558.4 D22.2 D28.1 J1_PCIE0.56 J1_PCIE0.58 J1_PCIE0.M J1_PCIE2.56 J1_PCIE2.58 J1_PCIE2.M J1_PCIE4.56 J1_PCIE4.58 J1_PCIE4.M J14.3 J27.5 J27.6 J27.7 J27.8 J27.11 J27.13 J27.17 J27.19 J27.20 J27.22 J27.23 J27.24 J27.25 J27.26 J27.28 J27.30 J27.32 J27.34 J27.36 J27.40 J27.42 J27.44 J27.46 J27.48 J27.56 J27.58 J27.59 J27.M J28.MH1 J28.MH2 J32. J33. J33.17 J34. J34.17 J35. J35.17 MP1_PCIE0.1 MP1_PCIE1.1 MP1_PCIE2.1 MP1_PCIE3.1 MP1_PCIE4.1 MP2_PCIE0.1 MP2_PCIE1.1 MP2_PCIE2.1 MP2_PCIE3.1 MP2_PCIE4.1 MP3_PCIE0.1 MP3_PCIE1.1 MP3_PCIE2.1 MP3_PCIE3.1 MP3_PCIE4.1 P12.11 R100.1 R100.2 R133.2 R134.2 R135.2 R136.2 R137.2 R138.2 R141.2 R142.2 R145.2 R146.2 R147.2 R148.2 R151.2 R152.2 R654.1 R776.1 R777.1 T21.MH1 T21.MH2 T35. U1.A12 U1.A13 U1.A14 U1.A15 U1.A16 U1.A17 U1.A19 U1.AA8 U1.AA16 U1.AA17 U1.AA26 U1.AA30 U1.AB5 U1.AB6 U1.AB8 U1.AB16 U1.AB18 U1.AB19 U1.AB20 U1.AB21 U1.AB29 U1.AC7 U1.AC8 U1.AC13 U1.AC16 U1.AC17 U1.AC18 U1.AC19 U1.AD7 U1.AD16 U1.AD17 U1.AD19 U1.AE7 U1.AE10 U1.AE12 U1.AE17 U1.AE18 U1.AE19 U1.AF1 U1.AF2 U1.AF13 U1.AF15 U1.AF16 U1.AF17 U1.AF18 U1.AG3 U1.AG4 U1.AG5 U1.AG6 U1.AG8 U1.AG9 U1.AG14 U1.AG15 U1.AG16 U1.AG18 U1.AG19 U1.AH1 U1.AH2 U1.AH3 U1.AH4 U1.AH6 U1.AH7 U1.AH8 U1.AH14 U1.AH16 U1.AH17 U1.AH18 U1.AJ6 U1.AJ7 U1.AJ14 U1.AJ15 U1.AJ16 U1.AJ17 U1.AJ27 U1.AK12 U1.AK14 U1.AK15 U1.AK16 U1.AK17 U1.AK18 U1.B12 U1.B14 U1.B15 U1.B16 U1.B19 U1.C12 U1.C13 U1.C14 U1.C16 U1.C17 U1.D12 U1.D14 U1.D15 U1.D16 U1.D17 U1.E12 U1.E13 U1.E14 U1.E15 U1.E17 U1.F12 U1.F13 U1.F15 U1.F16 U1.G13 U1.G14 U1.G15 U1.G16 U1.H12 U1.H13 U1.H14 U1.H16 U1.J12 U1.J14 U1.J15 U1.J16 U1.K11 U1.K13 U1.K14 U1.K15 U1.L14 U1.L15 U1.L25 U1.L26 U1.W9 U1.W10 U1.W26 U1.W27 U1.Y9 U1.Y27 U1.Y29 U1.Y30 U4.11 U5.11 U8.T4 U9.T4 U10.T4 U11.T4 U12.12 U12.13 U12.15 U12.16 U12.18 U12.19 U12.21 U12.22 U12.24 U12.25 U12.27 U12.28 U12.50 U13.9 U13.10 U13.12 U13.13 U13.15 U13.16 U13.18 U13.19 U13.21 U13.22 U13.24 U13.25 U13.27 U13.28 U13.30 U13.31 U13.33 U13.34 U13.42 U13.43 U14.42 U14.43 U16.5 U16.6 U16.10 U16.11 U16.18 U18.A3 U26_SPI_bridge2.14 U28_SPI_bridge2.12 U28_SPI_bridge2.13 U30.6 U30.7 U30.8 U31.3 U31.4 U31.8 U31.13 U31.14 U31.15 U31.16 U32.8 U32.13 U32.14 U32.15 U32.16 U33.7 U35_I2C_Expander1.7 U35_I2C_Expander1.10 U35_I2C_Expander2.7 U35_I2C_Expander2.10 U35_I2C_Expander3.7 U35_I2C_Expander3.10 U35_I2C_Expander?.7 U35_I2C_Expander?.10 U35_I2C_Expander_10.7 U35_I2C_Expander_10.10 U35_I2C_Expander_11.7 U35_I2C_Expander_11.10 U35_I2C_Expander_12.7 U35_I2C_Expander_12.10 U35_I2C_Expander_13.3 U35_I2C_Expander_13.7 U35_I2C_Expander_13.10 U35_I2C_Expander_13.22 U35_I2C_Expander_13.23 U35_I2C_Expander_14.7 U35_I2C_Expander_14.10 U35_I2C_Expander_15.7 U35_I2C_Expander_15.10 U35_I2C_Expander_16.7 U35_I2C_Expander_16.10 U39.18 U39.25 U39.26 U39.29 U39.32 U39.37 U39.38 U39.40 U40.6 U41.A1 U41.A2 U41.A7 U41.A8 U41.A9 U41.A10 U41.A11 U41.A12 U41.A13 U41.A14 U41.B1 U41.B7 U41.B8 U41.B9 U41.B10 U41.B11 U41.B12 U41.B13 U41.B14 U41.C1 U41.C3 U41.C5 U41.C7 U41.C8 U41.C9 U41.C10 U41.C11 U41.C12 U41.C13 U41.C14 U41.D1 U41.D2 U41.D3 U41.D4 U41.D12 U41.D13 U41.D14 U41.E1 U41.E2 U41.E3 U41.E5 U41.E8 U41.E9 U41.E10 U41.E12 U41.E13 U41.E14 U41.F1 U41.F2 U41.F3 U41.F10 U41.F12 U41.F13 U41.F14 U41.G1 U41.G2 U41.G3 U41.G10 U41.G12 U41.G13 U41.G14 U41.H1 U41.H2 U41.H3 U41.H5 U41.H12 U41.H13 U41.H14 U41.J1 U41.J2 U41.J3 U41.J12 U41.J13 U41.J14 U41.K1 U41.K2 U41.K3 U41.K6 U41.K7 U41.K10 U41.K12 U41.K13 U41.K14 U41.L1 U41.L2 U41.L3 U41.L12 U41.L13 U41.L14 U41.M1 U41.M2 U41.M3 U41.M7 U41.M8 U41.M9 U41.M10 U41.M11 U41.M12 U41.M13 U41.M14 U41.N1 U41.N3 U41.N6 U41.N7 U41.N8 U41.N9 U41.N10 U41.N11 U41.N12 U41.N13 U41.N14 U41.P1 U41.P2 U41.P7 U41.P8 U41.P9 U41.P10 U41.P11 U41.P12 U41.P13 U41.P14 U42.6 U44.8 U44.9 U45.12 U45.15 U45.16 U46.A3 U46.B3 U46.C4 U47.E2 U47.E4 U48.11 U55.22 U55.28 U55.29 U55.30 U55.32 U55.33 U55.34 U55.36 U55.43 U55.44 U55.45 U55.46 U55.53 U55.54 U55.55 U55.57 U55.58 U55.59 U55.60 U57.11 U57.12 U58.10 U58.11 U59_5V_to_3V3_for_FTDI.6 U59_U_5V_to_3V31.6 U59_U_5V_to_3V32.6 U59_U_5V_to_3V33.6 U60.8 U63.5 U65.1 U69.8 U73.3 U78.3 U78.4 U79.5 U79.6 U79.11 U79.12
copper on no net: | length 7.3
  L1 w0.098: v6(225.091,201.6) 225.591,202.099
  L1 w0.116: 199.987,179.781 v1(200.474,180.269) ; 205.243,187.935 v6(205.933,187.935) ; 205.854,217.78 v2(206.258,218.183) ; 208.877,185.572 v4(209.364,186.06) ; 211.071,218.189 211.468,217.792 v6(211.468,217.79) ; 211.328,189.497 v6(211.815,189.984)
  L5 (Sign) w0.116: v27(206.21,189.395) v27(207.231,188.374)
  L3 (Sign) w0.092: 211.935,218.405 v28(212.331,218.008)
  L3 (Sign) w0.098: 225.942,201.362 226.441,200.863 v28(226.441,200.862)
  other v1: 469.12,228.065 470.22,228.065 471.32,228.065 472.42,228.065 469.12,229.165 470.22,229.165 471.32,229.165 472.42,229.165 469.12,230.265 470.22,230.265 471.32,230.265 472.42,230.265 469.12,231.365 470.22,231.365 471.32,231.365 472.42,231.365
  other v2: 194.907,219.469
  other v3: 397.769,14.173 404.703,14.173 412.069,14.173 419.435,14.173 426.788,14.173 434.154,14.173 441.52,14.173 448.886,14.173 456.252,14.173 463.618,14.173 470.984,14.173 477.906,14.173 485.272,14.173 492.638,14.173 500.004,14.173 507.357,14.173 514.723,14.173 522.089,14.173 529.455,14.173 536.821,14.173 544.187,14.173 484.599,18.11 491.965,18.11 499.331,18.11 506.697,18.11 514.063,18.11 521.429,18.11 528.795,18.11 365.925,19.431 371.297,22.606 534.889,26.273 516.382,26.772 491.149,27.445 498.515,27.445 506.882,27.546 531.012,27.724 363.131,29.273 370.497,29.273 377.863,29.273 385.229,29.273 392.595,29.273 399.961,29.273 407.327,29.273 414.693,29.273 421.615,29.273 428.981,29.273 436.347,29.273 443.713,29.273 451.066,29.273 458.432,29.273 524.713,29.273 465.798,37.998 473.164,37.998 480.53,37.998 487.896,37.998 494.817,37.998 502.183,37.998 509.549,37.998 516.915,37.998 524.281,37.998 531.635,37.998 539.001,37.998 546.367,37.998 553.733,37.998 460.146,73.393 484.518,73.393 507.632,73.393 532.003,73.393 556.387,73.393 580.504,73.393 604.888,73.393 627.99,73.393 651.104,73.393 674.205,73.393 697.319,73.393 720.42,73.393 743.534,73.393 766.635,73.393 437.286,83.629 462.166,83.629 487.058,83.629 510.667,83.629 535.559,83.629 560.438,83.629 585.076,83.629 609.956,83.629 633.578,83.629 657.187,83.629 680.809,83.629 704.418,83.629 728.04,83.629 751.662,83.629 775.271,83.629 362.636,93.866 387.261,93.866 411.899,93.866 436.524,93.866 461.162,93.866 485.788,93.866 510.172,93.866 362.712,95.25 387.35,95.25 411.988,95.25 365.484,103.796 387.769,104.102 412.915,104.102 438.048,104.102 463.182,104.102 488.328,104.102 513.207,104.102 362.712,105.664 387.858,105.664 413.004,105.664 499.605,110.401 522.58,112.344 362.636,114.338 396.405,114.338 506.4,116.599 362.636,176.378 389.052,176.378 415.442,176.378 441.858,176.378 468.274,176.378 494.69,176.378 519.811,176.378 546.227,176.378 572.643,176.378 598.805,176.378 625.196,176.378 650.342,176.378 675.488,176.378 700.608,176.378 725.754,176.378 750.9,176.378 776.046,176.378 801.167,176.378 362.636,186.614 387.782,186.614 412.928,186.614 438.048,186.614 463.194,186.614 488.34,186.614 513.461,186.614 538.607,186.614 563.753,186.614 588.645,186.614 362.636,196.85 395.91,196.85 1269.987,1269.987 1269.987,1269.987 1269.987,1269.987 1269.987,1269.987
  other v16: 207.666,77.658 142.166,102.658 207.666,127.658 292.557,136.121 267.557,201.621 317.557,201.621 58.795,233.154 108.795,233.154 83.795,298.654
  other v20: 214.416,112.658 138.226,164.6 282.557,208.371 93.795,226.404
  other v21: 214.416,92.658 138.226,184.6 302.557,208.371 73.795,226.404
  other v29: 216.776,173.7
  other v31: 200.474,180.269

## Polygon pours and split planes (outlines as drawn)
Vout1_1 on L1 "VOUT1_1_L01_P031" (solid, remove dead copper, pour order 31): 198.844,67.084 211.096,67.084 211.096,91.973 198.619,91.973
eMMC_GND on L1 "EMMC_GND_L01_P032" (solid, remove dead copper, pour order 32): 211.295,44.484 215.995,44.484 215.995,47.461 216.907,47.461 216.907,59.796 214.738,59.796 214.738,63.539 215.445,63.539 215.445,67.103 215.995,67.103 215.995,91.973 211.487,91.973 211.487,67.084 212.495,67.084 212.495,63.539 212.77,63.539 212.77,59.796 210.106,59.796 210.106,47.461 211.254,47.461
Vout2_1 on L1 "VOUT2_1_L01_P030" (solid, remove dead copper, pour order 30): 216.412,67.103 228.867,67.103 228.867,91.992 216.412,91.904
SW2_1 on L1 "SW2_1_L01_P027" (solid, remove dead copper, pour order 27): 225.097,53.499 225.083,53.499 217.455,45.871 217.455,44.86 216.655,44.86 216.655,46.834 217.205,47.384 217.205,60.296 214.999,60.296 214.999,63.039 219.085,63.039 219.085,66.258 225.847,66.258 225.847,60.296 225.097,60.296
SW1_1 on L1 "SW1_1_L01_P025" (solid, remove dead copper, pour order 25): 202.037,53.546 209.616,45.967 209.616,44.959 210.116,44.959 210.216,44.86 210.259,44.902 210.259,46.886 210.076,46.886 209.851,47.111 209.851,53.543 209.851,60.296 212.495,60.296 212.495,63.039 209.383,63.039 209.383,67.696 202.037,67.696
PWR_OUT_20V on L1 "PWR_OUT_20V_L01_P021" (solid, remove dead copper, pour order 21): 102.179,43.118 100.185,41.123 ccw(c101.796,39.512) 99.517,39.512 99.517,39.204 cw(c98.65,39.204) 99.263,38.59 cw(c99.032,38.821) 99.032,38.495 97.259,38.495 ccw(c97.259,35.955) 95.463,37.751 91.927,34.215 cw(c90.131,36.011) 90.131,33.471 76.791,33.471 ccw(c76.791,32.736) 76.272,33.255 cw(c76.167,33.361) 76.167,33.212 71.975,33.212 ccw(c71.975,31.653) 70.872,32.755 70.279,32.162 cw(c68.98,33.461) 68.98,31.624 65.983,31.624 ccw(c65.983,31.582) 65.953,31.612 65.534,31.612 cw(c65.534,32.713) 64.755,31.934 cw(c64.832,32.011) 64.724,32.011 64.724,32.542 63.245,32.542 ccw(c63.245,32.115) 62.943,32.417 62.547,32.021 ccw(c62.636,31.932) 62.511,31.932 62.511,29.286 cw(c62.42,29.286) 62.484,29.221 ccw(c62.826,29.221) 62.826,28.88 64.328,28.88 ccw(c64.328,30.462) 65.91,30.462 cw(c66.36,30.462) 66.36,30.912 69.252,30.912 cw(c69.252,30.521) 69.643,30.521 ccw(c70.704,30.521) 70.704,29.46 92.816,29.46 cw(c92.816,28.27) 94.005,28.27 ccw(c96.404,28.27) 96.404,25.872 230.439,25.872 ccw(c230.439,26.669) 231.237,26.67 231.237,59.525 230.907,59.854 226.058,59.854 225.43,59.226 225.43,50.793 cw(c225.249,50.793) 225.249,50.613 ccw(c225.249,49.818) 224.455,49.818 224.455,35.736 cw(c223.374,35.736) 223.374,34.655 203.844,34.655 cw(c203.844,35.324) 203.176,35.324 203.176,49.157 ccw(c201.761,49.157) 201.761,50.571 201.642,50.571 cw(c201.642,50.818) 201.395,50.818 201.395,53.646 202.051,54.303 202.051,60.241 201.752,60.541 196.547,60.541 195.965,59.959 195.965,37.516 195.965,36.475 cw(c195.165,36.475) 195.165,35.675 184.806,35.675 184.172,35.602 cw(c184.172,38.014) 182.466,36.308 182.466,56.386 182.257,56.596 177.504,56.596 177.485,56.577 177.485,33.805 176.303,32.623 156.332,32.623 155.036,33.92 155.036,56.632 154.837,56.831 145.256,56.831 138.083,62.64 138.07,64.526 137.639,64.957 135.223,64.957 134.939,65.186 132.017,65.186 132.017,52.065 132.335,51.747 134.685,51.747 134.685,37.411 110.955,37.411 110.249,38.026 110.249,50.966 111.933,52.65 112.733,52.65 112.733,64.246 112.173,64.806 107.133,64.806 102.179,59.852
SW2_2 on L1 "SW2_2_L01_P050" (solid, remove dead copper, pour order 50): 176.494,51.025 176.494,56.969 178.468,56.969 178.867,57.368 178.867,62.227 178.077,63.018 174.412,63.018 170.944,59.55 168.022,59.55 167.856,59.384 167.856,57.447 168.249,57.447 169.206,56.49 169.206,51.13
eMMC_GND on L1 "EMMC_GND_L01_P046" (solid, pour order 46): 164.908,40.815 164.908,43.928 163.113,45.723 163.113,56.905 163.311,57.103 163.866,57.103 164.266,57.503 164.266,63.064 162.814,64.516 162.814,90.047 169.247,90.047 169.247,64.516 167.881,63.109 167.695,57.35 167.866,57.179 168.541,57.179 168.801,56.919 168.801,45.068 167.158,43.273 167.158,40.815
SW1_2 on L1 "SW1_2_L01_P047" (solid, remove dead copper, pour order 47): 155.303,51.105 155.303,57.049 153.329,57.049 152.93,57.448 152.93,62.307 153.721,63.097 157.385,63.097 160.853,59.629 163.775,59.629 164.266,59.138 164.266,57.503 163.866,57.103 163.124,57.103 162.591,56.569 162.591,51.21
eMMC_GND on L1 "EMMC_GND_L01_P003" (solid, pour order 3): 121.102,51.746 121.102,75.376 120.127,76.351 120.127,90.808 124.878,90.808 124.878,87.857 124.879,76.468 123.977,75.566 123.977,51.746
SW2 on L1 "SW2_L01_P002" (solid, pour order 2): 132.017,52.283 132.017,71.526 124.57,71.526 124.57,66.585 124.57,52.283
SW1 on L1 "SW1_L01_P000" (solid, pour order 0): 112.916,51.746 112.916,71.526 120.477,71.526 120.477,66.048 120.477,51.746
3.3V_LN_1 on L1 "3.3V_LN_1_L01_P065" (solid, remove dead copper, pour order 65): 293.335,198.481 296.618,198.481 296.618,195.834 296.642,195.81 296.634,195.801 293.335,195.801
eMMC_VccQ on L1 "EMMC_VCCQ_L01_P115" (solid, remove dead copper, pour order 115): 111.756,188.415 111.148,188.415 cw(c111.148,189.22) 110.343,189.22 110.343,189.588 cw(c110.957,189.588) 110.957,190.202 113.453,190.202 cw(c113.453,189.421) 114.234,189.421 114.234,189.058 cw(c113.584,189.058) 113.584,188.409 111.875,188.409 cw(c111.875,189.626)
eMMC_VccQ on L1 "EMMC_VCCQ_L01_P113" (solid, remove dead copper, pour order 113): 110.84,194.647 111.65,194.647 cw(c111.65,194.114) 112.184,194.114 112.184,193.591 cw(c111.64,193.591) 111.64,193.048 111.296,193.048 cw(c111.296,193.552) 110.792,193.552 109.113,193.552 cw(c109.113,193.848) 108.817,193.848 108.817,194.198 cw(c109.267,194.198) 109.267,194.648 110.819,194.648 cw(c110.819,194.182)
5V_RAIL on L1 "5V_RAIL_L01_P111" (solid, remove dead copper, pour order 111): 104.129,199.369 105.932,199.369 cw(c105.932,198.485) 106.816,198.485 106.816,197.135 cw(c106.216,197.135) 106.216,196.535 ccw(c106.216,196.3) 105.981,196.3 105.981,195.638 ccw(c106.567,195.638) 106.567,195.052 cw(c106.567,194.802) 106.817,194.802 106.817,192.548 cw(c106.517,192.548) 106.517,192.248 106.204,192.248 cw(c106.204,193.873) 104.579,193.873 104.579,196.427 ccw(c104.379,196.427) 104.379,196.627 cw(c104.379,196.877) 104.129,196.877
eMMC_Vcc on L1 "EMMC_VCC_L01_P110" (solid, remove dead copper, pour order 110): 117.391,200.376 cw(c117.391,197.898) 119.87,197.898 119.87,196.849 cw(c118.72,196.849) 118.72,195.699 117.4,195.699 cw(c117.4,196.329) 116.77,196.329 116.77,196.565 ccw(c115.798,196.567) 115.8,197.539 cw(c115.728,198.264) 115.728,197.535 114.778,197.535 ccw(c114.778,197.335) 114.578,197.335 cw(c114.478,197.335) 114.478,197.235 112.303,197.235 cw(c112.303,197.989) 111.549,197.989 ccw(c111.428,197.989) 111.428,198.11 110.692,198.11 ccw(c110.667,198.11) 110.667,198.135 109.116,198.135 cw(c109.116,198.435) 108.816,198.435 108.816,198.485 cw(c109.266,198.485) 109.266,198.935 109.651,198.935 ccw(c109.651,199.51) 110.226,199.51 110.226,200.069 cw(c110.533,200.069) 110.533,200.376
no net on L1 "NONET_L01_P109" (solid, pour order 109): 108.816,198.485
V_PoE+ on L1 "V_POE+_L01_P101" (solid, remove dead copper, pour order 101): 27.833,84.726 27.833,89.932 cw(c30.373,89.932) 30.373,92.472 30.458,92.472 cw(c30.458,90.698) 32.233,90.698 32.233,85.692 ccw(c33.147,85.692) 33.147,84.777 36.877,84.777 ccw(c36.877,86.037) 38.136,86.037 38.136,87.344 cw(c38.786,87.344) 38.786,87.994 40.191,87.994 cw(c40.191,87.494) 40.691,87.494 40.691,85.004 cw(c38.151,85.004) 38.151,82.464 30.094,82.464 cw(c30.094,84.726)
1V0@1.5A on L1 "1V0@1.5A_L01_P099" (solid, remove dead copper, pour order 99): 185.259,123.688 186.02,124.45 190.181,124.45 190.346,124.285 190.346,123.785 190.136,123.575 186.465,123.575 185.928,123.038 185.259,123.038
1V8@1.5A on L1 "1V8@1.5A_L01_P098" (solid, remove dead copper, pour order 98): 185.059,128.985 185.76,128.985 186.608,129.833 186.62,129.82 190.181,129.82 190.381,129.62 190.381,128.939 190.044,128.602 186.681,128.602 186.364,128.285 185.076,128.285 185.059,128.268
3V3_Rail on L1 "3V3_RAIL_L01_P097" (solid, remove dead copper, pour order 97): 180.197,124.15 183.459,124.15 183.459,122.674 183.448,122.684 180.197,122.684
3V3_Rail on L1 "3V3_RAIL_L01_P096" (solid, remove dead copper, pour order 96): 180.137,129.168 183.359,129.168 183.359,127.8 183.348,127.81 180.137,127.81
2V5@1.5A on L1 "2V5@1.5A_L01_P094" (solid, remove dead copper, pour order 94): 185.259,133.784 186.391,134.644 190.02,134.644 190.581,134.083 190.581,133.415 190.111,132.945 187.735,132.945 187.446,133.234 185.459,133.234 185.259,133.434
3V3_Rail on L1 "3V3_RAIL_L01_P093" (solid, remove dead copper, pour order 93): 180.147,133.834 180.547,133.834 183.459,133.834 183.459,132.634 183.448,132.645 180.147,132.645
Vout_2_Selector on L1 "VOUT_2_SELECTOR_L01_P092" (solid, remove dead copper, pour order 92): 67.867,32.312 67.867,31.801 65.041,31.801 64.832,32.011 64.832,41.398 65.433,42 69.449,42 71.603,44.154 77.05,44.154 77.31,44.414 89.841,44.414 89.841,41.009 89.382,40.55 69.255,40.555 68.515,41.295 66.76,41.295 66.76,41.25 66.584,41.074 66.584,37.558 66.785,37.358 66.785,33.394
no net on L1 "NONET_L01_P091" (solid, pour order 91): 240.974,253.666 243.299,253.666 243.873,254.24 243.873,254.786 245.114,254.786 245.124,254.776 245.124,254.256 244.955,254.256 244.349,253.65 244.349,252.8 243.716,252.8 242.724,251.808 242.724,251.233 242.849,251.108 241.599,251.108 241.587,251.808
12V_HiSpeed on L1 "12V_HISPEED_L01_P090" (solid, remove dead copper, pour order 90): 241.249,244.523 241.25,244.523 243.512,244.523 243.549,244.561 243.549,245.548 243.35,245.548 242.849,246.048 242.849,247.008 241.599,247.008 241.249,246.658
3.3V_PS_Config on L1 "3.3V_PS_CONFIG_L01_P089" (solid, remove dead copper, pour order 89): 227.389,260.147 227.389,265.23 235.595,265.23 235.82,265.005 235.82,259.846 235.454,259.48 228.057,259.48
US+_Vcc_PS_DDR_504 on L1 "US+_VCC_PS_DDR_504_L01_P088" (solid, remove dead copper, pour order 88): 228.142,237.479 228.264,237.601 233.752,237.601 234.415,236.939 235.697,236.939 235.697,236.489 234.909,235.701 233.564,235.701 233.564,235.532 233.121,235.089 233.121,232.687 233.121,232.686 226.311,232.686 225.275,233.723 225.275,237.479
ADP1741_3.6V on L1 "ADP1741_3.6V_L01_P087" (solid, remove dead copper, pour order 87): 218.502,243.909 218.527,243.934 229.115,243.934 229.115,241.784 223.928,241.784 223.366,241.221 223.366,240.621 218.502,240.621
FPGA_Vcc_HD on L1 "FPGA_VCC_HD_L01_P086" (solid, remove dead copper, pour order 86): 219.871,255.655 222.399,255.655 222.726,255.982 222.726,256.791 225.008,256.791 225.046,256.753 225.046,255.551 225.196,255.401 229.065,255.401 229.065,253.026 229.115,252.976 221.261,252.976 220.621,253.616 220.621,254.216 220.21,254.216 219.871,254.555
NetC616_1 on L1 "NETC616_1_L01_P085" (solid, remove dead copper, pour order 85): 250.396,248.603 250.396,249.303 247.195,249.299 246.968,249.433 246.876,249.433 244.524,249.433 244.524,249.183 246.268,249.183 246.848,248.603
NetC603_1 on L1 "NETC603_1_L01_P084" (solid, remove dead copper, pour order 84): 252.38,250.233 252.373,250.226 247.239,250.226 246.946,249.933 244.524,249.933 244.524,249.683 250.673,249.683 250.83,249.526 250.837,249.533 252.38,249.533
NetC605_1 on L1 "NETC605_1_L01_P083" (solid, remove dead copper, pour order 83): 252.38,250.758 247.301,250.758 246.726,250.183 244.524,250.183 244.524,250.433 246.351,250.433 247.376,251.458 252.38,251.458
NetC612_1 on L1 "NETC612_1_L01_P082" (solid, remove dead copper, pour order 82): 247.914,252.624 250.496,252.624 250.496,251.749 250.492,251.752 246.968,251.752 245.899,250.683 244.524,250.683 244.524,250.933 245.449,250.933 247.126,252.611
NetD19_2 on L1 "NETD19_2_L01_P081" (solid, remove dead copper, pour order 81): 241.424,247.433 240.524,247.433 239.746,246.655 239.746,243.317 239.187,242.759 239.187,240.836 239.949,240.836 239.949,242.106 240.714,242.872 240.714,246.473 241.424,247.183
NetD19_1 on L1 "NETD19_1_L01_P080" (solid, remove dead copper, pour order 80): 238.718,242.908 238.718,240.368 237.452,239.101 234.782,239.101 233.564,239.101 233.564,238.651 233.264,238.351 230.914,238.351 228.314,238.351 228.314,239.051 228.264,239.101 228.264,241.001 229.467,241.001 231.208,242.741 235.72,242.741 237.337,244.359 237.734,245.041 238.668,247.132 239.219,247.683 239.95,247.683 240.2,247.933 241.424,247.933 241.424,247.683 240.724,247.683 240.366,247.682 239.42,246.728 239.42,243.609
NetD16_2 on L1 "NETD16_2_L01_P079" (solid, remove dead copper, pour order 79): 235.887,245.787 236.649,245.787 238.804,247.942 239.904,247.942 240.146,248.183 241.424,248.183 241.424,248.433 240.724,248.433 240.135,248.432 239.842,248.183 237.208,248.183 235.887,247.057
NetD16_1 on L1 "NETD16_1_L01_P078" (solid, remove dead copper, pour order 78): 222.815,248.084 234.634,248.084 235.57,248.808 239.842,248.808 239.967,248.933 241.424,248.933 241.424,248.683 240.724,248.683 240.607,248.565 240.125,248.565 240.059,248.499 236.797,248.499 235.252,246.954 235.252,245.151 231.986,245.151 222.865,245.151
NetD17_1 on L1 "NETD17_1_L01_P077" (solid, remove dead copper, pour order 77): 230.352,249.038 230.14,248.826 222.815,248.826 222.815,251.578 235.252,251.578 235.252,249.793 235.612,249.433 241.424,249.433 241.424,249.183 239.818,249.183 239.673,249.038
